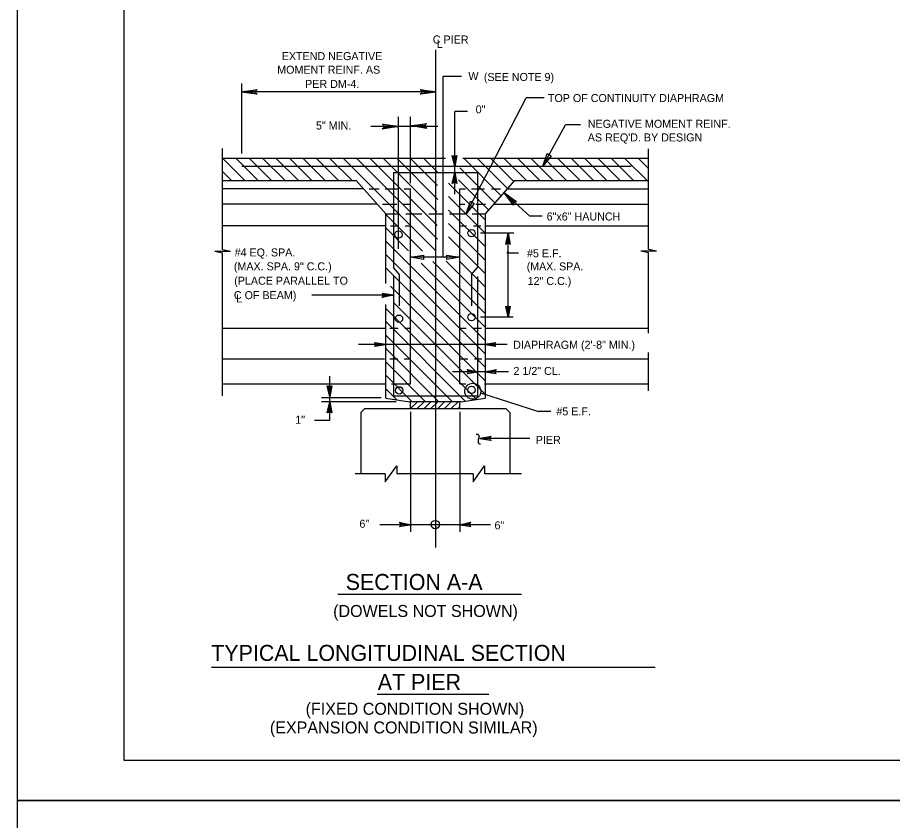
# Model space of a CAD drawing. Extents: x 639980 to 641204, y 298038 to 300414.
# Drawn here: x 639980.3 to 640308.1, y 299812.3 to 300113 of the extents above; entities that cross this region are included whole.
import ezdxf

# ---------------------------------------------------------------- set-up
doc = ezdxf.new("R2010")
doc.units = 0
doc.layers.add('2', color=7, linetype='Continuous')
doc.layers.add('PLT-BNDY', color=7, linetype='Continuous')

msp = doc.modelspace()

# ---------------------------------------------------------------- linework, layer by layer
at = {"layer": '2'}
for p, q in [((640020.31, 299834.78), (640020.31, 300398.78)), ((640136.85, 300100.87), (640136.85, 299914.52)), ((640139.83, 300023.32), (640139.83, 300090.92)), ((640146.64, 300090.92), (640139.83, 300090.92)), ((640064.4, 300062.12), (640064.4, 300088.37)), ((640136.85, 300085.22), (640064.4, 300085.22)), ((640148.36, 300039.53), (640170.81, 300082.95)), ((640177.62, 300082.95), (640170.81, 300082.95)), ((640148.94, 300077.78), (640144.08, 300077.78)), ((640144.08, 300057.17), (640144.08, 300077.78)), ((640123.04, 300026.42), (640123.04, 300075.77)), ((640127.55, 300051.02), (640127.55, 300075.77)), ((640137.79, 300072.17), (640112.7, 300072.17)), ((640177.14, 300057.39), (640185.54, 300072.88)), ((640191.16, 300072.88), (640185.54, 300072.88)), ((640057.05, 300026.12), (640057.05, 300063.92)), ((640216.65, 300026.27), (640216.65, 300063.8)), ((640057.05, 300059.95), (640057.43, 300060.32)), ((640057.05, 300060.32), (640057.05, 300060.32)), ((640057.05, 300060.32), (640065.45, 300051.92)), ((640057.05, 300060.32), (640140.63, 300060.32)), ((640062.07, 300060.32), (640070.47, 300051.92)), ((640067.1, 300060.32), (640075.5, 300051.92)), ((640072.12, 300060.32), (640080.52, 300051.92)), ((640077.14, 300060.32), (640085.54, 300051.92)), ((640082.17, 300060.32), (640090.57, 300051.92)), ((640087.19, 300060.32), (640095.59, 300051.92)), ((640092.21, 300060.32), (640100.61, 300051.92)), ((640097.24, 300060.32), (640105.64, 300051.92)), ((640102.26, 300060.32), (640137, 300025.59)), ((640107.28, 300060.32), (640137.59, 300030.02)), ((640112.31, 300060.32), (640137.56, 300035.07)), ((640117.33, 300060.32), (640137.42, 300040.23)), ((640122.35, 300060.32), (640137.79, 300044.89)), ((640127.38, 300060.32), (640137.59, 300050.11)), ((640132.4, 300060.32), (640137.96, 300054.76)), ((640147.17, 300060.32), (640216.65, 300060.32)), ((640147.47, 300060.32), (640161.52, 300046.28)), ((640152.49, 300060.32), (640163.88, 300048.93)), ((640157.52, 300060.32), (640166.25, 300051.59)), ((640162.54, 300060.32), (640170.94, 300051.92)), ((640167.56, 300060.32), (640175.96, 300051.92)), ((640172.59, 300060.32), (640180.99, 300051.92)), ((640177.61, 300060.32), (640186.01, 300051.92)), ((640182.63, 300060.32), (640191.03, 300051.92)), ((640187.66, 300060.32), (640196.06, 300051.92)), ((640192.68, 300060.32), (640201.08, 300051.92)), ((640197.7, 300060.32), (640206.1, 300051.92)), ((640202.73, 300060.32), (640211.13, 300051.92)), ((640207.75, 300060.32), (640216.15, 300051.92)), ((640212.77, 300060.32), (640216.65, 300056.44)), ((640057.05, 300055.3), (640060.43, 300051.92)), ((640210.16, 300057.17), (640064.4, 300057.17)), ((640121.1, 300055.03), (640152.6, 300055.03)), ((640121.1, 300055.03), (640121.1, 300019.37)), ((640144.08, 300055.06), (640144.08, 300057.17)), ((640144.08, 300046.85), (640144.08, 300055.03)), ((640146, 300056.77), (640159.15, 300043.62)), ((640152.6, 300055.03), (640152.6, 300019.37)), ((640057.05, 300051.92), (640107.15, 300051.92)), ((640118.25, 300039.47), (640107.15, 300051.92)), ((640145.52, 300052.23), (640156.78, 300040.97)), ((640166.55, 300051.92), (640155.45, 300039.47)), ((640166.55, 300051.92), (640216.65, 300051.92)), ((640109.85, 300048.92), (640057.05, 300048.92)), ((640112.1, 300048.92), (640115.82, 300048.92)), ((640118.08, 300048.92), (640122.7, 300048.92)), ((640125.18, 300048.92), (640127.55, 300048.92)), ((640127.55, 299975.87), (640127.55, 300048.92)), ((640141.76, 300050.96), (640155.45, 300037.27)), ((640146, 299975.87), (640146, 300048.92)), ((640146, 300048.92), (640148.19, 300048.92)), ((640150.33, 300048.92), (640155.29, 300048.92)), ((640157.89, 300048.92), (640161.3, 300048.92)), ((640163.85, 300048.92), (640216.65, 300048.92)), ((640141.76, 300045.94), (640155.45, 300032.25)), ((640162.65, 300047.42), (640172.25, 300038.57)), ((640114.95, 300043.07), (640057.05, 300043.07)), ((640117.05, 300043.07), (640122.47, 300043.07)), ((640124.84, 300043.07), (640127.55, 300043.07)), ((640146, 300043.07), (640147.85, 300043.07)), ((640151.97, 300043.07), (640155.63, 300043.07)), ((640158.75, 300043.07), (640216.65, 300043.07)), ((640118.25, 300039.47), (640123.35, 300039.47)), ((640118.25, 300013.43), (640118.25, 300039.47)), ((640118.25, 300039.31), (640132.06, 300025.5)), ((640125.75, 300039.47), (640131.75, 300039.47)), ((640134.45, 300039.47), (640139.4, 300039.47)), ((640141.76, 300040.91), (640155.45, 300027.23)), ((640142.1, 300039.47), (640148.47, 300039.47)), ((640150.65, 300039.47), (640155.45, 300039.47)), ((640155.45, 300039.47), (640155.45, 299970.47)), ((640176.9, 300038.57), (640172.25, 300038.57)), ((640117.95, 300034.97), (640057.05, 300034.97)), ((640120, 300034.97), (640123.15, 300034.97)), ((640125.52, 300034.97), (640127.55, 300034.97)), ((640141.76, 300035.89), (640155.45, 300022.2)), ((640146, 300034.97), (640148.53, 300034.97)), ((640151.12, 300034.97), (640153.94, 300034.97)), ((640155.75, 300034.97), (640216.65, 300034.97)), ((640118.25, 300034.29), (640126.84, 300025.7)), ((640151.25, 300031.82), (640151.25, 300031.82)), ((640166.19, 300032.27), (640153.8, 300032.27)), ((640164.11, 300000.77), (640164.11, 300032.27)), ((640118.25, 300029.26), (640155.45, 299992.06)), ((640141.76, 300030.87), (640155.45, 300017.18)), ((640054.2, 300025.52), (640060.05, 300025.52)), ((640054.2, 300025.52), (640057.05, 300024.92)), ((640057.05, 300026.12), (640060.05, 300025.52)), ((640057.05, 299971.37), (640057.05, 300024.92)), ((640213.8, 300025.67), (640219.65, 300025.67)), ((640213.8, 300025.67), (640216.65, 300025.07)), ((640216.65, 300026.27), (640219.65, 300025.67)), ((640216.65, 299994.76), (640216.65, 300025.07)), ((640118.25, 300024.24), (640155.45, 299987.04)), ((640146, 300023.25), (640127.55, 300023.25)), ((640135.89, 300021.67), (640155.45, 300002.11)), ((640140.83, 300021.75), (640155.45, 300007.13)), ((640145.77, 300021.84), (640155.45, 300012.16)), ((640164.11, 300024.89), (640168.01, 300024.89)), ((640118.25, 300019.22), (640155.45, 299982.02)), ((640123.26, 300016.85), (640121.1, 300019.37)), ((640131.47, 300021.07), (640155.45, 299997.09)), ((640150.33, 300016.73), (640152.6, 300019.37)), ((640121.1, 300016.2), (640121.1, 299971.37)), ((640123.26, 300016.85), (640123.26, 300005.03)), ((640150.33, 300016.73), (640150.33, 300005.03)), ((640152.6, 300016.08), (640152.6, 299971.37)), ((640120.09, 300012.35), (640155.45, 299976.99)), ((640120.92, 300009.09), (640090.57, 300009.09)), ((640118.25, 299970.47), (640118.25, 300005.52)), ((640121.24, 300006.18), (640155.45, 299971.97)), ((640118.31, 300004.08), (640152.38, 299970.01)), ((640118.25, 299999.12), (640148.02, 299969.36)), ((640166.05, 300000.77), (640153.8, 300000.77)), ((640057.05, 299996.72), (640118.4, 299996.72)), ((640119.77, 299996.72), (640122.93, 299996.72)), ((640125.41, 299996.72), (640127.55, 299996.72)), ((640146, 299996.72), (640148.41, 299996.72)), ((640151.01, 299996.72), (640154.17, 299996.72)), ((640155.75, 299996.72), (640216.65, 299996.72)), ((640118.25, 299994.1), (640143.23, 299969.12)), ((640118.25, 299990.57), (640108.05, 299990.57)), ((640155.45, 299990.57), (640118.25, 299990.57)), ((640118.25, 299989.08), (640138.2, 299969.12)), ((640163.7, 299990.57), (640155.45, 299990.57)), ((640216.65, 299973.17), (640216.65, 299987.57)), ((640057.05, 299985.17), (640117.8, 299985.17)), ((640118.25, 299984.05), (640133.18, 299969.12)), ((640119.77, 299985.17), (640122.81, 299985.17)), ((640125.18, 299985.17), (640127.55, 299985.17)), ((640146, 299985.17), (640148.98, 299985.17)), ((640151.46, 299985.17), (640154.28, 299985.17)), ((640155.45, 299985.17), (640216.65, 299985.17)), ((640118.25, 299979.03), (640128.16, 299969.12)), ((640164.3, 299980.35), (640143.3, 299980.35)), ((640057.05, 299975.87), (640118.4, 299975.87)), ((640097.25, 299970.62), (640097.25, 299978.72)), ((640120.45, 299975.87), (640127.55, 299975.87)), ((640146, 299975.87), (640148.25, 299975.87)), ((640155.3, 299975.87), (640216.65, 299975.87)), ((640118.25, 299974.01), (640122.42, 299969.84)), ((640116.6, 299970.62), (640094.25, 299970.62)), ((640097.25, 299962.23), (640097.25, 299970.62)), ((640118.25, 299970.63), (640118.44, 299970.44)), ((640118.25, 299970.47), (640127.1, 299969.12)), ((640121.1, 299971.37), (640152.6, 299971.37)), ((640146.45, 299969.12), (640155.45, 299970.47)), ((640153.8, 299972.42), (640175.5, 299965.42)), ((640122.15, 299969.12), (640094.25, 299969.12)), ((640108.95, 299965.07), (640110.45, 299966.57)), ((640110.45, 299966.57), (640163.25, 299966.57)), ((640146.45, 299969.12), (640127.1, 299969.12)), ((640127.55, 299966.57), (640127.55, 299969.12)), ((640127.55, 299969.12), (640127.55, 299969.12)), ((640127.55, 299969.12), (640127.55, 299969.12)), ((640127.55, 299969.12), (640127.55, 299969.12)), ((640127.55, 299966.58), (640130.1, 299969.12)), ((640130.09, 299966.57), (640132.64, 299969.12)), ((640132.64, 299966.57), (640135.19, 299969.12)), ((640135.18, 299966.57), (640137.73, 299969.12)), ((640137.73, 299966.57), (640140.28, 299969.12)), ((640140.27, 299966.57), (640142.82, 299969.12)), ((640142.82, 299966.57), (640145.37, 299969.12)), ((640145.37, 299966.57), (640146, 299967.21)), ((640146, 299966.57), (640146, 299969.12)), ((640164.75, 299965.07), (640163.25, 299966.57)), ((640108.95, 299965.07), (640108.95, 299942.12)), ((640127.55, 299965.33), (640127.55, 299920.37)), ((640146, 299965.33), (640146, 299920.37)), ((640164.75, 299965.07), (640164.75, 299942.12)), ((640180.15, 299965.42), (640175.5, 299965.42)), ((640091.54, 299962.23), (640097.25, 299962.23)), ((640172.25, 299955.32), (640153.5, 299955.32)), ((640118.1, 299939.12), (640122.45, 299945.12)), ((640122.45, 299945.12), (640122.45, 299942.12)), ((640150.95, 299939.12), (640155.3, 299945.12)), ((640155.3, 299945.12), (640155.3, 299942.12)), ((640118.1, 299942.12), (640106.75, 299942.12)), ((640118.1, 299942.12), (640118.1, 299939.12)), ((640150.95, 299942.12), (640122.45, 299942.12)), ((640150.95, 299942.12), (640150.95, 299939.12)), ((640169.1, 299942.12), (640155.3, 299942.12)), ((640136.85, 299931.02), (640136.85, 299931.02)), ((640157.55, 299923.07), (640116, 299923.07)), ((640100.27, 299897), (640169.13, 299897)), ((640053.01, 299869.67), (640219.14, 299869.67)), ((640115.01, 299859.55), (640156.89, 299859.55)), ((640806.31, 299834.78), (640020.31, 299834.78))]:
    msp.add_line(p, q, dxfattribs=at)
for points in [[(640069.8, 300084.47), (640069.65, 300084.92), (640064.4, 300085.22), (640069.8, 300084.47), (640070.1, 300084.32), (640064.4, 300085.22), (640069.65, 300085.37), (640069.8, 300085.82), (640064.4, 300085.22), (640070.1, 300086.12), (640069.8, 300085.82)], [(640131.45, 300085.82), (640131.6, 300085.52), (640136.85, 300085.22), (640131.45, 300085.82), (640131.15, 300086.12), (640136.85, 300085.22), (640131.6, 300084.92), (640131.45, 300084.47), (640136.85, 300085.22), (640131.15, 300084.32), (640131.45, 300084.47)], [(640117.35, 300072.92), (640117.5, 300072.47), (640122.75, 300072.17), (640117.35, 300072.92), (640117.05, 300073.07), (640122.75, 300072.17), (640117.5, 300071.87), (640117.35, 300071.57), (640122.75, 300072.17), (640117.05, 300071.27), (640117.35, 300071.57)], [(640133.26, 300071.82), (640133.11, 300072.12), (640127.86, 300072.42), (640133.26, 300071.82), (640133.56, 300071.52), (640127.86, 300072.42), (640133.11, 300072.72), (640133.26, 300073.02), (640127.86, 300072.42), (640133.56, 300073.32), (640133.26, 300073.02)], [(640144.68, 300061.07), (640144.23, 300061.07), (640144.08, 300057.17), (640144.68, 300061.07), (640144.83, 300061.37), (640144.08, 300057.17), (640143.78, 300061.07), (640143.48, 300061.07), (640144.08, 300057.17), (640143.18, 300061.37), (640143.48, 300061.07)], [(640143.48, 300051.13), (640143.78, 300051.28), (640144.08, 300055.03), (640143.48, 300051.13), (640143.18, 300050.83), (640144.08, 300055.03), (640144.23, 300051.28), (640144.68, 300051.13), (640144.08, 300055.03), (640144.83, 300050.83), (640144.68, 300051.13)], [(640166.1, 300043.22), (640166.25, 300043.52), (640162.65, 300047.42), (640166.1, 300043.22), (640166.1, 300042.77), (640162.65, 300047.42), (640166.55, 300043.97), (640167, 300044.12), (640162.65, 300047.42), (640167.3, 300044.12), (640167, 300044.12)], [(640163.51, 300028.37), (640163.81, 300028.52), (640164.11, 300032.27), (640163.51, 300028.37), (640163.21, 300028.07), (640164.11, 300032.27), (640164.26, 300028.52), (640164.71, 300028.37), (640164.11, 300032.27), (640164.86, 300028.07), (640164.71, 300028.37)], [(640117.02, 300009.69), (640117.17, 300009.24), (640120.92, 300009.09), (640117.02, 300009.69), (640116.87, 300009.84), (640120.92, 300009.09), (640117.17, 300008.79), (640117.02, 300008.49), (640120.92, 300009.09), (640116.87, 300008.19), (640117.02, 300008.49)], [(640164.71, 300004.67), (640164.26, 300004.67), (640164.11, 300000.77), (640164.71, 300004.67), (640164.86, 300004.97), (640164.11, 300000.77), (640163.81, 300004.67), (640163.51, 300004.67), (640164.11, 300000.77), (640163.21, 300004.97), (640163.51, 300004.67)], [(640114.2, 299991.17), (640114.35, 299990.87), (640118.25, 299990.57), (640114.2, 299991.17), (640114.05, 299991.32), (640118.25, 299990.57), (640114.35, 299990.27), (640114.2, 299989.97), (640118.25, 299990.57), (640114.05, 299989.82), (640114.2, 299989.97)], [(640159.35, 299989.97), (640159.2, 299990.27), (640155.45, 299990.57), (640159.35, 299989.97), (640159.5, 299989.82), (640155.45, 299990.57), (640159.2, 299990.72), (640159.35, 299991.17), (640155.45, 299990.57), (640159.5, 299991.32), (640159.35, 299991.17)], [(640148.85, 299980.95), (640149, 299980.65), (640152.75, 299980.35), (640148.85, 299980.95), (640148.7, 299981.25), (640152.75, 299980.35), (640149, 299980.2), (640148.85, 299979.75), (640152.75, 299980.35), (640148.7, 299979.6), (640148.85, 299979.75)], [(640159.5, 299979.75), (640159.35, 299980.2), (640155.45, 299980.35), (640159.5, 299979.75), (640159.65, 299979.6), (640155.45, 299980.35), (640159.35, 299980.65), (640159.5, 299980.95), (640155.45, 299980.35), (640159.65, 299981.25), (640159.5, 299980.95)], [(640097.85, 299974.97), (640097.4, 299974.82), (640097.25, 299970.92), (640097.85, 299974.97), (640098, 299975.12), (640097.25, 299970.92), (640096.95, 299974.82), (640096.65, 299974.97), (640097.25, 299970.92), (640096.35, 299975.12), (640096.65, 299974.97)], [(640096.65, 299965.22), (640096.95, 299965.22), (640097.25, 299969.12), (640096.65, 299965.22), (640096.35, 299964.92), (640097.25, 299969.12), (640097.4, 299965.37), (640097.7, 299965.22), (640097.25, 299969.12), (640098, 299964.92), (640097.7, 299965.22)], [(640157.55, 299954.72), (640157.4, 299955.17), (640153.5, 299955.32), (640157.55, 299954.72), (640157.7, 299954.57), (640153.5, 299955.32), (640157.4, 299955.62), (640157.55, 299955.92), (640153.5, 299955.32), (640157.7, 299956.22), (640157.55, 299955.92)], [(640123.65, 299923.67), (640123.8, 299923.37), (640127.55, 299923.07), (640123.65, 299923.67), (640123.35, 299923.97), (640127.55, 299923.07), (640123.8, 299922.92), (640123.65, 299922.47), (640127.55, 299923.07), (640123.35, 299922.32), (640123.65, 299922.47)], [(640149.9, 299922.47), (640149.75, 299922.92), (640146, 299923.07), (640149.9, 299922.47), (640150.05, 299922.32), (640146, 299923.07), (640149.75, 299923.37), (640149.9, 299923.67), (640146, 299923.07), (640150.05, 299923.97), (640149.9, 299923.67)]]:
    msp.add_lwpolyline(points, dxfattribs=at)
for points in [[(640180.17, 300061.27), (640177.14, 300057.39), (640178.75, 300062.04)], [(640151.39, 300043.41), (640148.36, 300039.53), (640149.97, 300044.18)], [(640132.41, 300022.44), (640127.55, 300023.25), (640132.41, 300024.05)], [(640141.14, 300024.07), (640146, 300023.25), (640141.14, 300022.45)], [(640141.14, 300024.07), (640146, 300023.25), (640141.14, 300022.45)]]:
    msp.add_lwpolyline(points, close=True, dxfattribs=at)
for centre, radius in [((640123.04, 300031.72), 1.38), ((640150.38, 300032.26), 1.38), ((640164.08, 300024.94), 0.273), ((640150.4, 300000.81), 1.38), ((640123.2, 300000.22), 1.38), ((640150.87, 299973.05), 3), ((640123.26, 299973.37), 1.38), ((640150.41, 299973.55), 1.38), ((640136.81, 299923.09), 1.6)]:
    msp.add_circle(centre, radius, dxfattribs=at)
msp.add_spline([(640152.15, 299956.97), (640152.75, 299956.97), (640153.05, 299956.67), (640153.2, 299956.07), (640153.05, 299955.47), (640152.9, 299954.87), (640152.9, 299954.27), (640152.9, 299953.67), (640153.35, 299953.37), (640153.8, 299953.37)], degree=3, dxfattribs=at)
at = {"layer": 'PLT-BNDY'}
for points in [[(639980.31, 300413.78), (640821.31, 300413.78), (640821.31, 299819.78), (639980.31, 299819.78)], [(639980.31, 299819.78), (640821.31, 299819.78), (640821.31, 299225.78), (639980.31, 299225.78)]]:
    msp.add_lwpolyline(points, close=True, dxfattribs=at)

# ---------------------------------------------------------------- texts
at = {"layer": '2'}
for s, height, p in [('C PIER', 3, (640135.89, 300103.29)), ('L', 3, (640137.34, 300101.67)), ('EXTEND NEGATIVE', 2.9999, (640079.3, 300097.06)), ('MOMENT REINF. AS', 2.9999, (640077.6, 300091.97)), ('W', 3, (640149.22, 300089.59)), ('(SEE NOTE 9)', 2.9999, (640155.01, 300089.25)), ('PER DM-4.', 3, (640088.06, 300086.65)), ('TOP OF CONTINUITY DIAPHRAGM', 2.9999, (640179.01, 300081.36)), ('0"', 3, (640151.95, 300077.13)), ('5" MIN.', 3, (640092.11, 300071.08)), ('NEGATIVE MOMENT REINF.', 2.9999, (640193.96, 300071.73)), ("AS REQ'D. BY DESIGN", 2.9999, (640193.93, 300066.61)), ('6"x6" HAUNCH', 2.9999, (640178.54, 300037)), ('#4 EQ. SPA.', 2.9999, (640061.64, 300023.54)), ('#5 E.F.', 3, (640171.16, 300023.22)), ('(MAX. SPA. 9" C.C.)', 2.9999, (640061.37, 300018.32)), ('(MAX. SPA.', 2.97, (640171.08, 300018.32)), ('(PLACE PARALLEL TO', 2.9999, (640061.5, 300012.95)), ('12" C.C.)', 3, (640171.4, 300012.83)), ('C OF BEAM)', 3, (640061.37, 300007.54)), ('L', 3, (640062.25, 300006.29)), ('DIAPHRAGM (2\'-8" MIN.) ', 2.9999, (640165.99, 299988.96)), ('2 1/2" CL.', 3, (640166.11, 299979.15)), ('#5 E.F.', 3, (640182.18, 299964.01)), ('1"', 3, (640084.37, 299960.86)), ('PIER', 3, (640174.48, 299953.31)), ('6"', 3, (640108.4, 299921.92)), ('6"', 3, (640159, 299921.32)), ('SECTION A-A', 6, (640103.26, 299898.62)), ('(DOWELS NOT SHOWN)', 4.5, (640098.55, 299888.5)), ('TYPICAL LONGITUDINAL SECTION', 6, (640052.89, 299872.05)), ('AT PIER', 6, (640115.26, 299861.17)), ('(FIXED CONDITION SHOWN)', 4.5, (640088.24, 299851.87)), ('(EXPANSION CONDITION SIMILAR)', 4.5, (640074.85, 299844.87))]:
    msp.add_text(s, height=height, dxfattribs=at).set_placement(p)

doc.saveas('drawing.dxf')
